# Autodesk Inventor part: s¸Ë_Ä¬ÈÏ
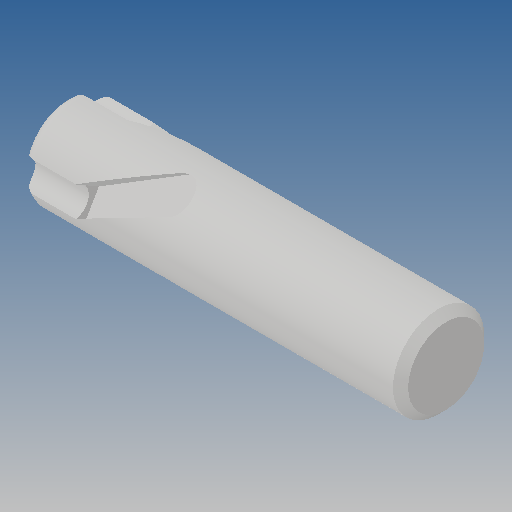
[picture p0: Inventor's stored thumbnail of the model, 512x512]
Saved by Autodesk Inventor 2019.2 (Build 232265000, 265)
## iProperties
Created: 2011-12
Part Number: s¸Ë_Ä¬ÈÏ
Material: Ogólny
Document SubType Name: Modeling
Designer: CADENGINEERING4
Density: 1 g/cm^3
Appearance: Domyślna
Author: CADENGINEERING4
Revision Number: ÈÎºÎ
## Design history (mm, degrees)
feature "NONE"
node "Bryła1"
